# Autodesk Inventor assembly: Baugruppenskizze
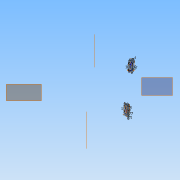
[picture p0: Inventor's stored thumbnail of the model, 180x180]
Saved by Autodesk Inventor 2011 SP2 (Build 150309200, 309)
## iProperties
Created: 2009-11
Part Number: Baugruppenskizze
Document SubType Name: Assembly
Designer: gkramp
d2: 0,000 mm
d4: 0,000 mm
d6: 0,000 mm
d8: 0,000 mm
d12: 0,000 mm
Author: gkramp
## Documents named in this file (3)
- D:\InventorSchulung\Zusammenbau_Beispiel_Master\Masterbaugruppe.iam
- D:\InventorSchulung\Zusammenbau_Beispiel_Master\BaugruppenMasterskizze.ipt
- D:\InventorSchulung\Zusammenbau_Beispiel_Master\Profilskizze.ipt
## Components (3 placed, 2 different names)
1. BaugruppenMasterskizze:1 — Passend:4, Passend:5
2. Profilskizze:1 — Fluchtend:1, Passend:4
3. Profilskizze:2 — Fluchtend:2, Passend:2, Passend:5
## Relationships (5: Mate 3, Flush 2)
- Fluchtend:1 [Flush]: Profilskizze:1
- Fluchtend:2 [Flush]: Profilskizze:2
- Passend:2 [Mate]: Profilskizze:2
- Passend:4 [Mate]: BaugruppenMasterskizze:1 ↔ Profilskizze:1
- Passend:5 [Mate]: BaugruppenMasterskizze:1 ↔ Profilskizze:2
